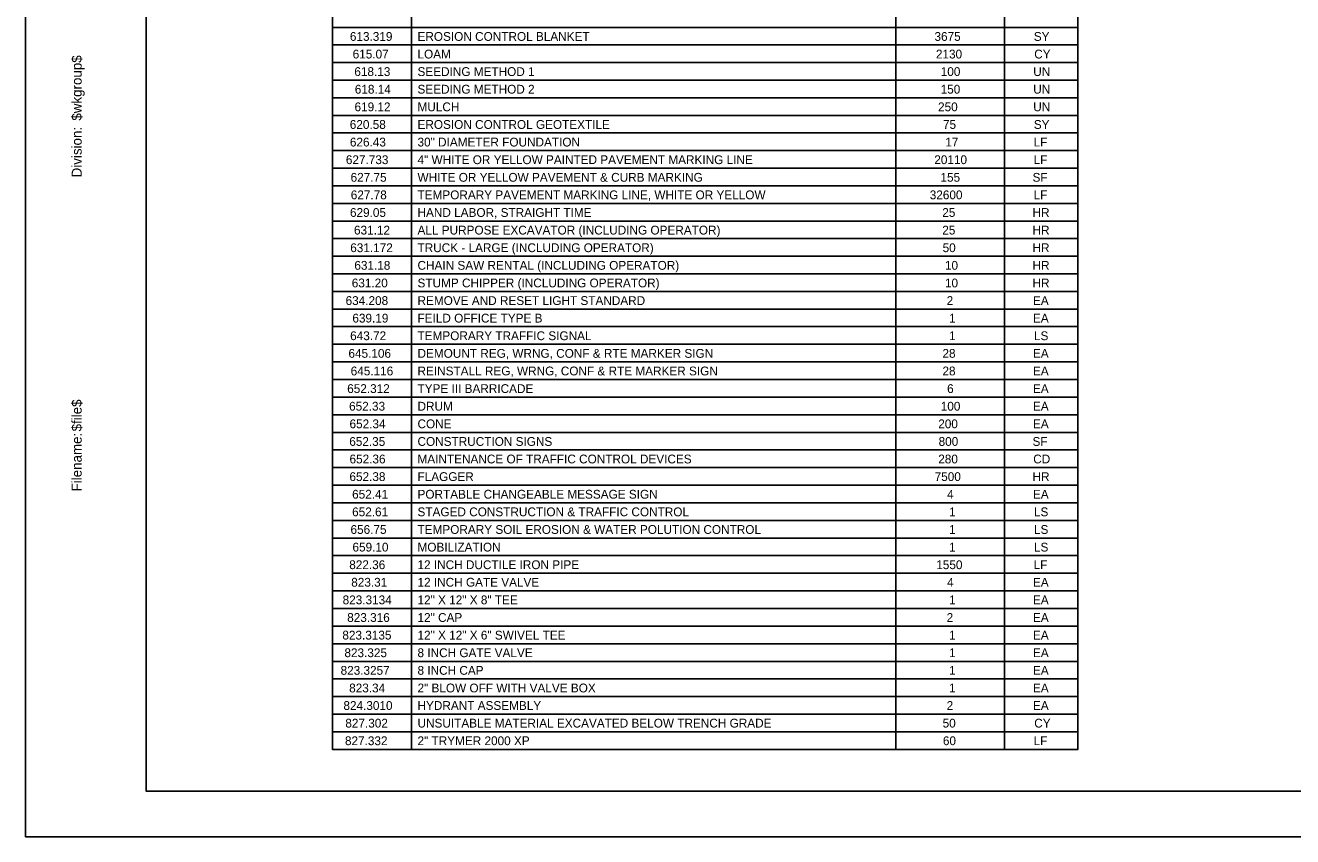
# Model space of a CAD drawing. Extents: x -0.13 to 2.7, y -0.05 to 1.78.
# Drawn here: x -0.135 to 1.282, y -0.051 to 0.856 of the extents above; entities that cross this region are included whole.
import ezdxf

# ---------------------------------------------------------------- set-up
doc = ezdxf.new("R2010")
doc.units = 0
for name, color, linetype in [('ANNOTATION', 7, 'Continuous'), ('BORDER', 7, 'Continuous'), ('PLOT BOUNDARY', 7, 'Continuous')]:
    doc.layers.add(name, color=color, linetype=linetype)

msp = doc.modelspace()

# ---------------------------------------------------------------- linework, layer by layer
at = {"layer": 'BORDER'}
for p, q in [((0.2969, 1.7003), (0.2969, 0.0465)), ((0.8383, 1.7003), (0.8383, 0.0465)), ((0.9596, 1.7003), (0.9596, 0.0465)), ((0.2083, 0.8538), (1.0417, 0.8538)), ((0.2083, 0.8341), (1.0417, 0.8341)), ((0.2083, 0.8144), (1.0417, 0.8144)), ((0.2083, 0.7948), (1.0417, 0.7948)), ((0.2083, 0.7751), (1.0417, 0.7751)), ((0.2083, 0.7554), (1.0417, 0.7554)), ((0.2083, 0.7357), (1.0417, 0.7357)), ((0.2083, 0.716), (1.0417, 0.716)), ((0.2083, 0.6963), (1.0417, 0.6963)), ((0.2083, 0.6766), (1.0417, 0.6766)), ((0.2083, 0.657), (1.0417, 0.657)), ((0.2083, 0.6373), (1.0417, 0.6373)), ((0.2083, 0.6176), (1.0417, 0.6176)), ((0.2083, 0.5979), (1.0417, 0.5979)), ((0.2083, 0.5782), (1.0417, 0.5782)), ((0.2083, 0.5585), (1.0417, 0.5585)), ((0.2083, 0.5388), (1.0417, 0.5388)), ((0.2083, 0.5192), (1.0417, 0.5192)), ((0.2083, 0.4995), (1.0417, 0.4995)), ((0.2083, 0.4798), (1.0417, 0.4798)), ((0.2083, 0.4601), (1.0417, 0.4601)), ((0.2083, 0.4404), (1.0417, 0.4404)), ((0.2083, 0.4207), (1.0417, 0.4207)), ((0.2083, 0.401), (1.0417, 0.401)), ((0.2083, 0.3814), (1.0417, 0.3814)), ((0.2083, 0.3617), (1.0417, 0.3617)), ((0.2083, 0.342), (1.0417, 0.342)), ((0.2083, 0.3223), (1.0417, 0.3223)), ((0.2083, 0.3026), (1.0417, 0.3026)), ((0.2083, 0.2829), (1.0417, 0.2829)), ((0.2083, 0.2632), (1.0417, 0.2632)), ((0.2083, 0.2435), (1.0417, 0.2435)), ((0.2083, 0.2238), (1.0417, 0.2238)), ((0.2083, 0.2041), (1.0417, 0.2041)), ((0.2083, 0.1844), (1.0417, 0.1844)), ((0.2083, 0.1647), (1.0417, 0.1647)), ((0.2083, 0.145), (1.0417, 0.145)), ((0.2083, 0.1253), (1.0417, 0.1253)), ((0.2083, 0.1056), (1.0417, 0.1056)), ((0.2083, 0.0859), (1.0417, 0.0859)), ((0.2083, 0.0662), (1.0417, 0.0662))]:
    msp.add_line(p, q, dxfattribs=at)
for points in [[(0, 1.75), (2.6667, 1.75), (2.6667, 0), (0, 0)], [(0.2083, 1.72), (1.0417, 1.72), (1.0417, 0.0465), (0.2083, 0.0465)]]:
    msp.add_lwpolyline(points, close=True, dxfattribs=at)
at = {"layer": 'PLOT BOUNDARY'}
msp.add_lwpolyline([(-0.1349, -0.051), (2.6984, -0.051), (2.6984, 1.7823), (-0.1349, 1.7823)], close=True, dxfattribs=at)

# ---------------------------------------------------------------- texts
at = {"layer": 'ANNOTATION'}
for s, height, p in [('613.319', 0.00984, (0.2279, 0.8387)), ('EROSION CONTROL BLANKET', 0.009843, (0.3035, 0.8387)), ('3675', 0.00984, (0.8814, 0.8387)), ('SY', 0.00984, (0.9924, 0.8387)), ('615.07', 0.00984, (0.231, 0.819)), ('LOAM', 0.00984, (0.3035, 0.819)), ('2130', 0.00984, (0.883, 0.819)), ('CY', 0.00984, (0.9929, 0.819)), ('618.13', 0.00984, (0.2329, 0.7994)), ('SEEDING METHOD 1', 0.009843, (0.3035, 0.7994)), ('100', 0.00984, (0.8884, 0.7994)), ('UN', 0.00984, (0.9918, 0.7994)), ('618.14', 0.00984, (0.2334, 0.7797)), ('SEEDING METHOD 2', 0.009843, (0.3035, 0.7797)), ('150', 0.00984, (0.8883, 0.7797)), ('UN', 0.00984, (0.9918, 0.7797)), ('619.12', 0.00984, (0.2331, 0.76)), ('MULCH', 0.00984, (0.3035, 0.76)), ('250', 0.00984, (0.8854, 0.76)), ('UN', 0.00984, (0.9918, 0.76)), ('620.58', 0.00984, (0.2278, 0.7403)), ('EROSION CONTROL GEOTEXTILE', 0.009843, (0.3035, 0.7403)), ('75', 0.00984, (0.8909, 0.7403)), ('SY', 0.00984, (0.9924, 0.7403)), ('626.43', 0.00984, (0.2279, 0.7206)), ('30" DIAMETER FOUNDATION', 0.009843, (0.3035, 0.7206)), ('17', 0.00984, (0.8935, 0.7206)), ('LF', 0.00984, (0.9922, 0.7206)), ('627.733', 0.00984, (0.2234, 0.7009)), ('4" WHITE OR YELLOW PAINTED PAVEMENT MARKING LINE', 0.009843, (0.3035, 0.7009)), ('20110', 0.00984, (0.8812, 0.7009)), ('LF', 0.00984, (0.9922, 0.7009)), ('627.75', 0.00984, (0.2287, 0.6812)), ('WHITE OR YELLOW PAVEMENT & CURB MARKING', 0.009843, (0.3035, 0.6812)), ('155', 0.00984, (0.8881, 0.6812)), ('SF', 0.00984, (0.991, 0.6812)), ('627.78', 0.00984, (0.2289, 0.6616)), ('TEMPORARY PAVEMENT MARKING LINE, WHITE OR YELLOW', 0.009843, (0.3035, 0.6616)), ('32600', 0.00984, (0.8761, 0.6616)), ('LF', 0.00984, (0.9922, 0.6616)), ('629.05', 0.00984, (0.228, 0.6419)), ('HAND LABOR, STRAIGHT TIME', 0.009843, (0.3035, 0.6419)), ('25', 0.00984, (0.8901, 0.6419)), ('HR', 0.00984, (0.991, 0.6419)), ('631.12', 0.00984, (0.2325, 0.6222)), ('ALL PURPOSE EXCAVATOR (INCLUDING OPERATOR)', 0.009843, (0.3035, 0.6222)), ('25', 0.00984, (0.8901, 0.6222)), ('HR', 0.00984, (0.991, 0.6222)), ('631.172', 0.00984, (0.2283, 0.6025)), ('TRUCK - LARGE (INCLUDING OPERATOR)', 0.009843, (0.3035, 0.6025)), ('50', 0.00984, (0.8905, 0.6025)), ('HR', 0.00984, (0.991, 0.6025)), ('631.18', 0.00984, (0.2329, 0.5828)), ('CHAIN SAW RENTAL (INCLUDING OPERATOR)', 0.009843, (0.3035, 0.5828)), ('10', 0.00984, (0.8931, 0.5828)), ('HR', 0.00984, (0.991, 0.5828)), ('631.20', 0.00984, (0.23, 0.5631)), ('STUMP CHIPPER (INCLUDING OPERATOR)', 0.009843, (0.3035, 0.5631)), ('10', 0.00984, (0.8931, 0.5631)), ('HR', 0.00984, (0.991, 0.5631)), ('634.208', 0.00984, (0.2231, 0.5434)), ('REMOVE AND RESET LIGHT STANDARD', 0.009843, (0.3035, 0.5434)), ('2', 0.00984, (0.895, 0.5434)), ('EA', 0.00984, (0.9915, 0.5434)), ('639.19', 0.00984, (0.2307, 0.5238)), ('FEILD OFFICE TYPE B', 0.009843, (0.3035, 0.5238)), ('1', 0.00984, (0.8977, 0.5238)), ('EA', 0.00984, (0.9915, 0.5238)), ('643.72', 0.00984, (0.2282, 0.5041)), ('TEMPORARY TRAFFIC SIGNAL', 0.009843, (0.3035, 0.5041)), ('1', 0.00984, (0.8977, 0.5041)), ('LS', 0.00984, (0.9926, 0.5041)), ('645.106', 0.00984, (0.2263, 0.4844)), ('DEMOUNT REG, WRNG, CONF & RTE MARKER SIGN', 0.009843, (0.3035, 0.4844)), ('28', 0.00984, (0.8903, 0.4844)), ('EA', 0.00984, (0.9915, 0.4844)), ('645.116', 0.00984, (0.2288, 0.4647)), ('REINSTALL REG, WRNG, CONF & RTE MARKER SIGN', 0.009843, (0.3035, 0.4647)), ('28', 0.00984, (0.8903, 0.4647)), ('EA', 0.00984, (0.9915, 0.4647)), ('652.312', 0.00984, (0.2249, 0.445)), ('TYPE III BARRICADE', 0.009843, (0.3035, 0.445)), ('6', 0.00984, (0.8955, 0.445)), ('EA', 0.00984, (0.9915, 0.445)), ('652.33', 0.00984, (0.227, 0.4253)), ('DRUM', 0.00984, (0.3035, 0.4253)), ('100', 0.00984, (0.8884, 0.4253)), ('EA', 0.00984, (0.9915, 0.4253)), ('652.34', 0.00984, (0.2275, 0.4056)), ('CONE', 0.00984, (0.3035, 0.4056)), ('200', 0.00984, (0.8856, 0.4056)), ('EA', 0.00984, (0.9915, 0.4056)), ('652.35', 0.00984, (0.2272, 0.3859)), ('CONSTRUCTION SIGNS', 0.009843, (0.3035, 0.3859)), ('800', 0.00984, (0.886, 0.3859)), ('SF', 0.00984, (0.991, 0.3859)), ('652.36', 0.00984, (0.2275, 0.3663)), ('MAINTENANCE OF TRAFFIC CONTROL DEVICES', 0.009843, (0.3035, 0.3663)), ('280', 0.00984, (0.8856, 0.3663)), ('CD', 0.00984, (0.9918, 0.3663)), ('652.38', 0.00984, (0.2274, 0.3466)), ('FLAGGER', 0.00984, (0.3035, 0.3466)), ('7500', 0.00984, (0.8816, 0.3466)), ('HR', 0.00984, (0.991, 0.3466)), ('652.41', 0.00984, (0.2304, 0.3269)), ('PORTABLE CHANGEABLE MESSAGE SIGN', 0.009843, (0.3035, 0.3269)), ('4', 0.00984, (0.8955, 0.3269)), ('EA', 0.00984, (0.9915, 0.3269)), ('652.61', 0.00984, (0.2304, 0.3072)), ('STAGED CONSTRUCTION & TRAFFIC CONTROL', 0.009843, (0.3035, 0.3072)), ('1', 0.00984, (0.8977, 0.3072)), ('LS', 0.00984, (0.9926, 0.3072)), ('656.75', 0.00984, (0.2286, 0.2875)), ('TEMPORARY SOIL EROSION & WATER POLUTION CONTROL', 0.009843, (0.3035, 0.2875)), ('LS', 0.00984, (0.9926, 0.2875)), ('1', 0.00984, (0.8977, 0.2875)), ('659.10', 0.00984, (0.2308, 0.2678)), ('MOBILIZATION', 0.009843, (0.3035, 0.2678)), ('1', 0.00984, (0.8977, 0.2678)), ('LS', 0.00984, (0.9926, 0.2678)), ('822.36', 0.00984, (0.2272, 0.2481)), ('12 INCH DUCTILE IRON PIPE', 0.009843, (0.3035, 0.2481)), ('1550', 0.00984, (0.8834, 0.2481)), ('LF', 0.00984, (0.9922, 0.2481)), ('823.31', 0.00984, (0.2294, 0.2285)), ('12 INCH GATE VALVE', 0.009843, (0.3035, 0.2285)), ('4', 0.00984, (0.8955, 0.2285)), ('EA', 0.00984, (0.9915, 0.2285)), ('823.3134', 0.00984, (0.2198, 0.2088)), ('12" X 12" X 8" TEE', 0.009843, (0.3035, 0.2088)), ('1', 0.00984, (0.8977, 0.2088)), ('EA', 0.00984, (0.9915, 0.2088)), ('823.316', 0.00984, (0.2249, 0.1891)), ('12" CAP', 0.00984, (0.3035, 0.1891)), ('2', 0.00984, (0.895, 0.1891)), ('EA', 0.00984, (0.9915, 0.1891)), ('823.3135', 0.00984, (0.2195, 0.1694)), ('12" X 12" X 6" SWIVEL TEE', 0.009843, (0.3035, 0.1694)), ('1', 0.00984, (0.8977, 0.1694)), ('EA', 0.00984, (0.9915, 0.1694)), ('823.325', 0.00984, (0.2218, 0.1497)), ('8 INCH GATE VALVE', 0.009843, (0.3035, 0.1497)), ('1', 0.00984, (0.8977, 0.1497)), ('EA', 0.00984, (0.9915, 0.1497)), ('823.3257', 0.00984, (0.2175, 0.13)), ('8 INCH CAP', 0.00984, (0.3035, 0.13)), ('1', 0.00984, (0.8977, 0.13)), ('EA', 0.00984, (0.9915, 0.13)), ('823.34', 0.00984, (0.2271, 0.1103)), ('2" BLOW OFF WITH VALVE BOX', 0.009843, (0.3035, 0.1103)), ('1', 0.00984, (0.8977, 0.1103)), ('EA', 0.00984, (0.9915, 0.1103)), ('824.3010', 0.00984, (0.2207, 0.0907)), ('HYDRANT ASSEMBLY', 0.009843, (0.3035, 0.0907)), ('2', 0.00984, (0.895, 0.0907)), ('EA', 0.00984, (0.9915, 0.0907)), ('827.302', 0.00984, (0.2228, 0.071)), ('UNSUITABLE MATERIAL EXCAVATED BELOW TRENCH GRADE', 0.009843, (0.3035, 0.071)), ('50', 0.00984, (0.8905, 0.071)), ('CY', 0.00984, (0.9929, 0.071)), ('827.332', 0.00984, (0.2224, 0.0513)), ('2" TRYMER 2000 XP', 0.009843, (0.3035, 0.0513)), ('60', 0.00984, (0.8908, 0.0513)), ('LF', 0.00984, (0.9922, 0.0513))]:
    msp.add_text(s, height=height, dxfattribs=at).set_placement(p)
at = {"layer": 'BORDER'}
for s, p in [('$wkgroup$', (-0.0719, 0.7495)), ('Division:', (-0.0719, 0.6861)), ('$file$', (-0.0719, 0.4021)), ('Filename:', (-0.0719, 0.335))]:
    msp.add_text(s, height=0.01116, rotation=90, dxfattribs=at).set_placement(p)

doc.saveas('drawing.dxf')
